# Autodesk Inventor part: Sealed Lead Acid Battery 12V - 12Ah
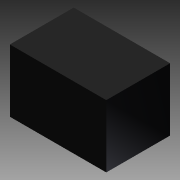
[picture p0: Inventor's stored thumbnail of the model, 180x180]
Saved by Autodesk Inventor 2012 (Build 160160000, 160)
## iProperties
Created: 2014-02
Part Number: Sealed Lead Acid Battery 12V - 12Ah
Material: Default
Document SubType Name: Modeling
Designer: Aser
Density: 1 g/cm^3
Author: Aser
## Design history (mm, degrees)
sketch "Sketch1"
  geometry: L1 (0, 0)-(98, 0); L2 (98, 0)-(98, -100); L3 (98, -100)-(0, -100); L4 (0, -100)-(0, 0)
  constraints: 8 end point, 2 parallel, 1 horizontal, 1 perpendicular
  dimensions: "d0" = 98 distance of L2.end L3.end; "d1" = 100 distance of L1.end L2.end
extrude "Extrusion1" new body sketch "Sketch1" distance "d2" = 151; taper "d3" = 0 deg
body "Solid1"
